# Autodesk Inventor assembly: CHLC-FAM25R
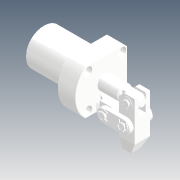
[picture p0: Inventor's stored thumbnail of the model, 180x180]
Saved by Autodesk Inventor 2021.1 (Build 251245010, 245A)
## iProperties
Created: 2019-04
Part Number: CHLC-FAM25R
Description: STEP AP214
Document SubType Name: Assembly
Designer: user
Title: CHLC-FAM25R.STEP
Revision Number: ÈÎºÎ
Sending System: SolidWorks 2016
Preprocessor: SwSTEP 2.0
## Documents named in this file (10)
- D:\Vault_2016\Projekty\Clamptek\Hydraulic\CHLC\CHLC-25\Inventor\CHLC-FAM25R\CHLC-FAM25R.iam
- D:\Vault_2016\Projekty\Clamptek\Hydraulic\CHLC\CHLC-25\Inventor\CHLC-FAM25R\CHLC-FAM25BT.ipt
- D:\Vault_2016\Projekty\Clamptek\Hydraulic\CHLC\CHLC-25\Inventor\CHLC-FAM25R\CHLC-25CX.ipt
- D:\Vault_2016\Projekty\Clamptek\Hydraulic\CHLC\CHLC-25\Inventor\CHLC-FAM25R\CHLC-25DX.ipt
- D:\Vault_2016\Projekty\Clamptek\Hydraulic\CHLC\CHLC-25\Inventor\CHLC-FAM25R\CHLC-25HSG.ipt
- D:\Vault_2016\Projekty\Clamptek\Hydraulic\CHLC\CHLC-25\Inventor\CHLC-FAM25R\CHLC-25KKDC.ipt
- D:\Vault_2016\Projekty\Clamptek\Hydraulic\CHLC\CHLC-25\Inventor\CHLC-FAM25R\CHLC-25LG.ipt
- D:\Vault_2016\Projekty\Clamptek\Hydraulic\CHLC\CHLC-25\Inventor\CHLC-FAM25R\CHLC-25ZC-HAN.ipt
- D:\Vault_2016\Projekty\Clamptek\Hydraulic\CHLC\CHLC-25\Inventor\CHLC-FAM25R\CHLC-25ZC.ipt
- D:\Vault_2016\Projekty\Clamptek\Hydraulic\CHLC\CHLC-25\Inventor\CHLC-FAM25R\Ñ¹±Û.ipt
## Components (16 placed, 16 different names)
1. CHLC-FAM25BT_1
2. CHLC-25CX_2
3. CHLC-25DX_3
4. CHLC-25HSG_4
5. CHLC-25KKDC_5
6. CHLC-25KKDC_6
7. CHLC-25LG_7
8. CHLC-25ZC-HAN_8
9. CHLC-25LG_9
10. CHLC-25ZC_10
11. CHLC-25KKDC_11
12. CHLC-25KKDC_12
13. CHLC-25KKDC_13
14. CHLC-25KKDC_14
15. CHLC-25CX_15
16. Ñ¹±Û_16
